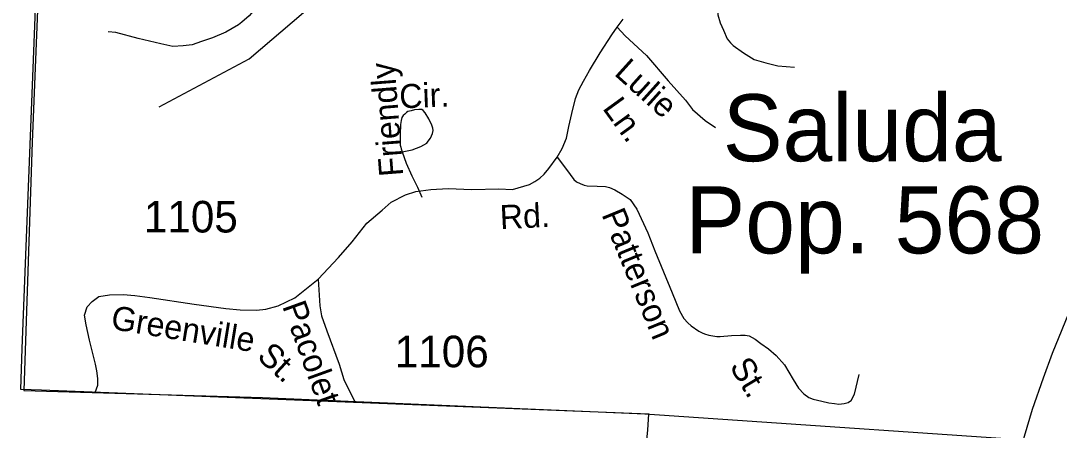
# Model space of a CAD drawing. Extents: x 990631 to 1056237, y 535999 to 585651.
# Drawn here: x 997020 to 1001128, y 554837 to 556457 of the extents above; entities that cross this region are included whole.
import ezdxf

# ---------------------------------------------------------------- set-up
doc = ezdxf.new("R2010")
doc.units = 0
for name, color, linetype in [('Exist Boundary Political City Limit New', 7, 'Continuous'), ('Exist Boundary Political CountyLine', 7, 'Continuous'), ('Exist Civil Demographics City Label', 7, 'Continuous'), ('Exist Hydrographic Creek Single Shore', 7, 'Continuous'), ('Exist Railroad Mainline', 7, 'Continuous'), ('Exist Road Non-System Type 51', 7, 'Continuous'), ('Exist Road Non-System Type 51 Label', 7, 'Continuous'), ('Exist Road Secondary Type 51 Attributed', 7, 'Continuous'), ('Exist Road Secondary Type 51 Label', 7, 'Continuous'), ('Exist Road Secondary Type 51 Number Label', 7, 'Continuous')]:
    doc.layers.add(name, color=color, linetype=linetype)

msp = doc.modelspace()

# ---------------------------------------------------------------- linework, layer by layer
at = {"layer": 'Exist Boundary Political City Limit New'}
for points in [[(997287.3, 562212.8), (997193.9, 561589.8), (997116.1, 561508), (997182.2, 561453.4), (997213.4, 561410.6), (997240.6, 561391.1), (997271.8, 561371.7), (997473.4, 560867.4), (997258.8, 560880.4), (997248.1, 560565.8), (997215.4, 559766.4), (997165.4, 558509.2), (997096.1, 556728.4), (997064.9, 555976.8), (997032.1, 554993.6), (997976.4, 554966.1)], [(997976.4, 554966.1), (999489.1, 554901.9), (1001301.9, 554778.2)]]:
    msp.add_lwpolyline(points, dxfattribs=at)
at = {"layer": 'Exist Boundary Political CountyLine'}
for points in [[(998707, 546620.1), (998768.4, 547288.4), (998835.1, 547966.7), (998916.8, 548792.5), (998991.2, 549584.6), (999111.7, 550801.4), (999167.8, 551397.9), (999229.7, 552060.2), (999297, 552754.5), (999373.1, 553532.6), (999431, 554135), (999500.6, 554839.1), (999504.7, 554901), (997102.8, 554995.1), (997020.3, 554998), (997026.3, 555160.3), (997250.5, 560876.2), (1000082.8, 560713.6), (1000385.5, 563731), (1000441.4, 564287.1), (1000460.4, 564476.5), (1000472.3, 564594.7), (1000608.5, 565973.2)], [(998637.8, 545891.8), (998696.2, 546502.4), (998768.4, 547288.4), (998835.1, 547966.7), (998916.8, 548792.5), (998991.2, 549584.6), (999111.7, 550801.4), (999167.8, 551397.9), (999229.7, 552060.2), (999297, 552754.5), (999373.1, 553532.6), (999431, 554135), (999500.6, 554839.1), (999504.7, 554901), (997102.8, 554995.1), (997020.3, 554998), (997026.3, 555160.3), (997250.5, 560876.2), (1000082.8, 560713.6), (1000385.5, 563731), (1000441.4, 564287.1), (1000460.4, 564476.5), (1000472.3, 564594.7), (1000608.5, 565973.2)]]:
    msp.add_lwpolyline(points, dxfattribs=at)
at = {"layer": 'Exist Hydrographic Creek Single Shore'}
msp.add_lwpolyline([(997567.5, 556116.7), (997924, 556306.5), (998138.5, 556489.2), (998316.9, 556833.5), (998298.7, 557043.9), (998252.9, 557169.5), (997955.4, 557497.1), (997854, 557709.2), (997724.7, 557830), (997568.6, 557902.1), (997360.5, 557947.5)], dxfattribs=at)
msp.add_lwpolyline([(997567.5, 556116.7), (997924, 556306.5), (998138.5, 556489.2), (998316.9, 556833.5), (998298.7, 557043.9), (998252.9, 557169.5), (997955.4, 557497.1), (997854, 557709.2), (997724.7, 557830), (997568.6, 557902.1), (997360.5, 557947.5)], dxfattribs=at)
at = {"layer": 'Exist Railroad Mainline'}
msp.add_lwpolyline([(1001176, 555327.6), (1001099.8, 555140.1), (1001064.4, 555043.2), (1001020.3, 554918.4), (1000943.4, 554656.9)], dxfattribs=at)
at = {"layer": 'Exist Road Non-System Type 51'}
for points in [[(999846.4, 556744.9), (999829.4, 556715.4), (999812.2, 556678), (999791.9, 556612.6), (999777.9, 556553), (999774.7, 556513.1), (999777.4, 556481), (999786.4, 556448.6), (999799.6, 556420.4), (999814.3, 556385.6), (999827.8, 556369.4), (999837.6, 556359), (999878.6, 556329.5), (999921.7, 556304.1), (999967.2, 556290.5), (1000015, 556279), (1000080.7, 556272.8)], [(998092.2, 556711.5), (998065.3, 556686.2), (998036.3, 556657.2), (998019.6, 556635.7), (997998.4, 556602.6), (997983.2, 556564.8), (997968.2, 556533.3), (997949.2, 556506.1), (997924.2, 556476.8), (997895.3, 556451.8), (997880.9, 556440.3), (997831.9, 556411.9), (997779.2, 556389.7), (997734.7, 556375.2), (997698.2, 556362.3), (997662.1, 556357.5), (997621.9, 556354.9), (997574.3, 556366.4), (997484.9, 556387.4), (997395.7, 556410.5), (997365.8, 556413.5)], [(999379.7, 556432.2), (999410.4, 556397.2), (999495.9, 556320.2), (999580.7, 556219.5), (999650.2, 556143.1), (999677, 556106.1), (999727.6, 556062.5), (999768.6, 556035.1)], [(998528.7, 555938.2), (998568.9, 555947), (998585.2, 555952.5), (998603.4, 555959.7), (998625.9, 555973.1), (998632.2, 555981), (998640.4, 555992.6), (998649, 556010.4), (998651.4, 556022.2), (998649.9, 556032.4), (998646.3, 556044.5), (998635, 556068.9), (998619.9, 556093.4), (998612.2, 556101.6), (998606.3, 556105.9), (998594.3, 556106.2), (998578.3, 556104.7), (998564, 556101.2), (998551.9, 556097.6), (998545.9, 556093.9), (998539.5, 556088.1), (998533.4, 556082.2), (998527.1, 556074.5), (998524.8, 556062.6), (998522.3, 556046.6), (998520.9, 556008.6), (998521.5, 555964.6), (998523.3, 555956.6), (998525, 555950.5), (998528.7, 555938.2)], [(998528.7, 555938.2), (998545.2, 555893.7), (998567.4, 555843), (998590.1, 555798.2), (998606.7, 555759.6)], [(999142.3, 555917.9), (999178.7, 555868.7), (999207.5, 555829.5), (999219.1, 555819.3), (999233, 555812.8), (999248.7, 555806.3), (999260.6, 555803.8), (999300.6, 555802.4), (999332.6, 555801.4), (999348.5, 555796.9), (999370.1, 555788.2), (999399.6, 555771.2), (999431, 555750.2), (999457.6, 555711.2), (999500.5, 555617.7), (999528.3, 555546.7), (999596.8, 555380.3), (999626.4, 555309.3), (999643.3, 555278.7), (999658.8, 555262.2), (999672.4, 555249.7), (999701.8, 555228.7), (999715.6, 555222.3), (999725.3, 555217.9), (999741.3, 555213.3), (999757.2, 555210.8), (999773.2, 555208.3), (999787.2, 555207.8), (999831.3, 555212.3), (999867.3, 555213.2), (999885.3, 555212.6), (999901.2, 555210.1), (999924.8, 555197.2), (999948.2, 555180.3), (999977.6, 555159.5), (1000008.7, 555132.3), (1000041.6, 555095.2), (1000075.6, 555038.1), (1000096.5, 555003.3), (1000117.7, 554980.7), (1000137.2, 554966.1), (1000155, 554959.3), (1000188.9, 554952.2), (1000216.6, 554945.5), (1000238.5, 554942.6), (1000256.5, 554940.1), (1000276.6, 554943.2), (1000292.6, 554946.7), (1000298.9, 554950.6), (1000305, 554954.5), (1000317.9, 554980), (1000336.5, 555057.5)]]:
    msp.add_lwpolyline(points, dxfattribs=at)
at = {"layer": 'Exist Road Secondary Type 51 Attributed'}
for points in [[(998196.3, 555434.5), (998276.6, 555520.4), (998330.7, 555582.7), (998388.9, 555656.8), (998449.4, 555707.2), (998485.6, 555739.5), (998542.1, 555767.7), (998582.4, 555781.8), (998642.9, 555789.9), (998711.4, 555793.9), (998804.1, 555789.9), (998910.9, 555791.9), (998966, 555789.6), (999010.3, 555802.1), (999032.7, 555809.4), (999053.1, 555820.8), (999073.6, 555834), (999090.1, 555849.5), (999108.8, 555872.9), (999142.3, 555917.9), (999161.6, 555951.3), (999178.8, 555992.7), (999188.3, 556038.4), (999200.2, 556089.9), (999214.2, 556149.7), (999227.3, 556183.2), (999246.4, 556218.6), (999269.8, 556259.8), (999312.3, 556330.6), (999358.7, 556400.8), (999379.7, 556432.2), (999402.8, 556463.6)], [(997315.1, 554986.7), (997324.7, 555014.8), (997324.7, 555041.8), (997320.7, 555072.4), (997316.4, 555099), (997292, 555193.6), (997279.6, 555254.5), (997272.6, 555291.6), (997283.6, 555324.7), (997302.7, 555346.7), (997329.5, 555366.4), (997371.5, 555372.4), (997425.4, 555373.5), (997472, 555370.5), (997530.2, 555362), (997706.5, 555335.7), (997830.8, 555318.9), (997888.4, 555313.9), (997953.1, 555312.4), (997989.1, 555316.6), (998038.8, 555329.2), (998104.9, 555361.2), (998196.3, 555434.5)], [(998196.3, 555434.5), (998203.9, 555329.3), (998210, 555289.6), (998231.3, 555230.1), (998280.1, 555099), (998298.4, 555037.9), (998342.4, 554946.5)]]:
    msp.add_lwpolyline(points, dxfattribs=at)

# ---------------------------------------------------------------- texts
at = {"layer": 'Exist Civil Demographics City Label'}
for s, p in [('Saluda', (999797.1, 555901.2)), ('Pop. 568', (999649.4, 555536.7))]:
    msp.add_text(s, height=265, dxfattribs=at).set_placement(p)
at = {"layer": 'Exist Road Non-System Type 51 Label'}
for s, rotation, p in [('Friendly', 94.4871, (998533.6, 555844.4)), ('Friendly', 94.4871, (998533.6, 555844.4)), ('Lulie', 318.004, (999363.8, 556245.2)), ('Lulie', 318.004, (999363.8, 556245.2)), ('Cir.', 2.2229, (998519.3, 556110.2)), ('Cir.', 2.2229, (998519.3, 556110.2)), ('Ln.', 306.0138, (999318.6, 556110.5)), ('Ln.', 306.0138, (999318.6, 556110.5)), ('Patterson', 292.3602, (999316.5, 555690.8)), ('Patterson', 292.3602, (999316.5, 555690.8)), ('St.', 300.813, (999821.8, 555089.8)), ('St.', 300.813, (999821.8, 555089.8))]:
    msp.add_text(s, height=95, rotation=rotation, dxfattribs=at).set_placement(p)
at = {"layer": 'Exist Road Secondary Type 51 Label'}
for s, rotation, p in [('Rd.', 2.8133, (998917.5, 555632.2)), ('Rd.', 2.8133, (998917.5, 555632.2)), ('Pacolet', 289.8697, (998053.7, 555328.1)), ('Pacolet', 289.8697, (998053.7, 555328.1)), ('Greenville', 350.7508, (997373.2, 555237.8)), ('Greenville', 350.7508, (997373.2, 555237.8)), ('St.', 317.365, (997950.6, 555123.9)), ('St.', 317.365, (997950.6, 555123.9))]:
    msp.add_text(s, height=95, rotation=rotation, dxfattribs=at).set_placement(p)
at = {"layer": 'Exist Road Secondary Type 51 Number Label'}
for s, p in [('1105', (997507, 555619.3)), ('1106', (998499.6, 555086.1))]:
    msp.add_text(s, height=125, dxfattribs=at).set_placement(p)

doc.saveas('drawing.dxf')
